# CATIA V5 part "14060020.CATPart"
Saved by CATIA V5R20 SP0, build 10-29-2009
Part number: 14060020
Definition: NONE
Nomenclature: 14060020
Source: Unknown
Description: 14060020
Bounding box of the stored display mesh (mm): x -10 to 40, y -44 to 33.913, z -34.1 to 34.1
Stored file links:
  C:\Users\Utente\Desktop\IO LAVORO\3D X SITO CF\X SITO\PLASTICA\RF2\14060020.CATPart
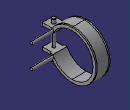
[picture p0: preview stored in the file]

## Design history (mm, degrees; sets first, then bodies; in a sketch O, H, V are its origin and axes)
Body1 "14060020" (main body)
  Solid1: solid without history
